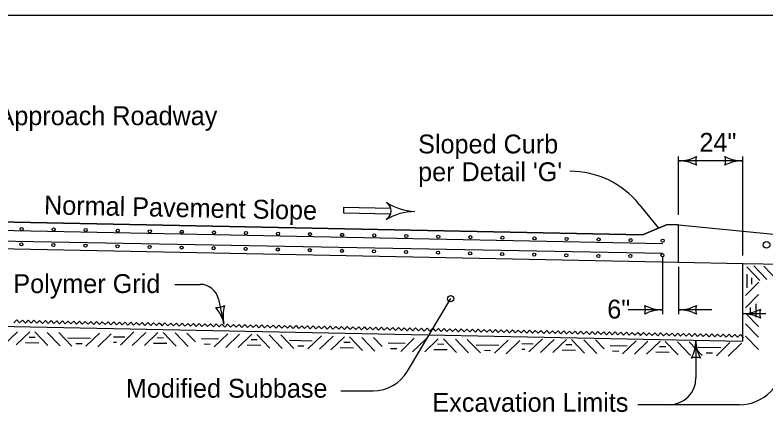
# Model space of a CAD drawing. Extents: x -2135039 to -2120895, y -2139150 to -2136566.
# Drawn here: x -2123840 to -2123042, y -2137468 to -2137036 of the extents above; entities that cross this region are included whole.
import ezdxf

# ---------------------------------------------------------------- set-up
doc = ezdxf.new("R2010")
doc.units = 0
for name, color, linetype in [('dsnCellElements', 7, 'Continuous'), ('Level 1', 7, 'Continuous'), ('Level 2', 7, 'Continuous'), ('Level 3', 7, 'Continuous')]:
    doc.layers.add(name, color=color, linetype=linetype)

msp = doc.modelspace()

# ---------------------------------------------------------------- linework, layer by layer
at = {"layer": 'dsnCellElements'}
msp.add_circle((-2123041.76, -2137279.72), 3.54, dxfattribs=at)
at = {"layer": 'Level 1'}
msp.add_lwpolyline([(-2124134.46, -2137035.95), (-2120999.47, -2137035.95), (-2120999.47, -2139045.94), (-2124134.46, -2139045.94)], close=True, dxfattribs=at)
at = {"layer": 'Level 2'}
for p, q in [((-2123135.19, -2137248.08), (-2123135.19, -2137185.93)), ((-2123067.14, -2137190.66), (-2123135.19, -2137190.66)), ((-2123067.14, -2137290.93), (-2123067.14, -2137185.93)), ((-2123176.93, -2137236.91), (-2123156.66, -2137262.08)), ((-2123440.9, -2137246.72), (-2123440.9, -2137246.72)), ((-2123440.84, -2137240.86), (-2123440.84, -2137240.86)), ((-2123173.47, -2137269.05), (-2123883.73, -2137254.79)), ((-2123883.73, -2137254.79), (-2123173.47, -2137269.05)), ((-2123883.73, -2137263.74), (-2123152.03, -2137278.43)), ((-2123147.96, -2137258.47), (-2123173.47, -2137269.05)), ((-2123173.47, -2137269.05), (-2123147.96, -2137258.47)), ((-2123135.19, -2137258.47), (-2123147.96, -2137258.47)), ((-2123135.19, -2137258.47), (-2123147.96, -2137258.47)), ((-2123135.19, -2137298.18), (-2123135.19, -2137258.47)), ((-2123135.19, -2137298.18), (-2123135.19, -2137258.47)), ((-2123135.19, -2137258.47), (-2123022.92, -2137269.7)), ((-2123884.3, -2137283.15), (-2123135.19, -2137298.18)), ((-2123883.16, -2137283.17), (-2123135.19, -2137298.18)), ((-2123152.21, -2137292.66), (-2123152.21, -2137353.4)), ((-2123135.19, -2137298.18), (-2123067.14, -2137299.55)), ((-2123135.19, -2137302.91), (-2123135.19, -2137353.4)), ((-2123067.14, -2137381.97), (-2123067.14, -2137299.55)), ((-2123067.14, -2137299.55), (-2122889.28, -2137303.12)), ((-2123062.64, -2137303.03), (-2123048.78, -2137317.45)), ((-2123055.42, -2137302.1), (-2123041.56, -2137316.52)), ((-2123044.56, -2137302.43), (-2123031.18, -2137316.36)), ((-2123064.1, -2137333.65), (-2123049.96, -2137319.51)), ((-2123670.01, -2137321.68), (-2123643.2, -2137321.68)), ((-2123064.33, -2137346.66), (-2123050.19, -2137332.52)), ((-2123623.67, -2137337.38), (-2123617.85, -2137363.75)), ((-2123622.24, -2137343.83), (-2123621.12, -2137348.94)), ((-2123423.08, -2137413.8), (-2123377.06, -2137336.83)), ((-2123152.21, -2137348.68), (-2123188.75, -2137348.68)), ((-2123099.97, -2137348.68), (-2123135.19, -2137348.68)), ((-2123064.33, -2137352.07), (-2123050.19, -2137366.21)), ((-2123042.42, -2137352.8), (-2123067.14, -2137352.8)), ((-2123883.73, -2137365.58), (-2123067.14, -2137381.97)), ((-2123064.33, -2137363.65), (-2123050.19, -2137377.79)), ((-2123837.07, -2137372), (-2123851.49, -2137385.86)), ((-2123824.06, -2137372.04), (-2123838.48, -2137385.89)), ((-2123818.65, -2137372.15), (-2123804.79, -2137386.57)), ((-2123805.64, -2137372.63), (-2123791.79, -2137387.06)), ((-2123793.19, -2137372.66), (-2123779.34, -2137387.08)), ((-2123749.98, -2137373.52), (-2123764.4, -2137387.38)), ((-2123737.53, -2137374), (-2123751.96, -2137387.85)), ((-2123713.44, -2137372.17), (-2123727.86, -2137386.02)), ((-2123701, -2137372.64), (-2123715.42, -2137386.5)), ((-2123687.99, -2137372.68), (-2123702.41, -2137386.53)), ((-2123682.58, -2137372.78), (-2123668.72, -2137387.21)), ((-2123669.57, -2137373.27), (-2123655.72, -2137387.69)), ((-2123657.12, -2137373.3), (-2123648.02, -2137382.77)), ((-2123613.91, -2137374.16), (-2123628.33, -2137388.02)), ((-2123601.46, -2137374.64), (-2123615.89, -2137388.49)), ((-2123588.45, -2137374.67), (-2123602.88, -2137388.53)), ((-2123583.04, -2137374.78), (-2123569.19, -2137389.21)), ((-2123570.04, -2137375.27), (-2123556.19, -2137389.69)), ((-2123557.59, -2137375.29), (-2123543.73, -2137389.72)), ((-2123514.38, -2137376.16), (-2123528.8, -2137390.02)), ((-2123501.93, -2137376.64), (-2123516.36, -2137390.49)), ((-2123489.88, -2137377.39), (-2123504.31, -2137391.25)), ((-2123484.47, -2137377.5), (-2123470.62, -2137391.92)), ((-2123471.47, -2137377.99), (-2123457.62, -2137392.41)), ((-2123459.02, -2137378.01), (-2123449.92, -2137387.49)), ((-2123415.8, -2137378.88), (-2123430.23, -2137392.74)), ((-2123403.36, -2137379.36), (-2123417.78, -2137393.21)), ((-2123390.35, -2137379.39), (-2123404.77, -2137393.25)), ((-2123384.94, -2137379.5), (-2123371.09, -2137393.92)), ((-2123371.94, -2137379.99), (-2123358.08, -2137394.41)), ((-2123359.49, -2137380.01), (-2123345.63, -2137394.43)), ((-2123316.27, -2137380.88), (-2123330.7, -2137394.73)), ((-2123303.83, -2137381.35), (-2123318.25, -2137395.21)), ((-2123279.74, -2137379.52), (-2123294.16, -2137393.37)), ((-2123267.29, -2137380), (-2123281.72, -2137393.85)), ((-2123254.28, -2137380.03), (-2123268.71, -2137393.89)), ((-2123248.87, -2137380.14), (-2123235.02, -2137394.56)), ((-2123235.87, -2137380.63), (-2123222.02, -2137395.05)), ((-2123223.42, -2137380.65), (-2123214.32, -2137390.12)), ((-2123180.2, -2137381.52), (-2123194.63, -2137395.37)), ((-2123167.76, -2137381.99), (-2123182.18, -2137395.85)), ((-2123154.75, -2137382.03), (-2123169.17, -2137395.88)), ((-2123149.34, -2137382.14), (-2123135.48, -2137396.56)), ((-2123136.34, -2137382.62), (-2123122.48, -2137397.05)), ((-2123123.89, -2137382.65), (-2123110.03, -2137397.07)), ((-2123116.82, -2137380.97), (-2123116.82, -2137420.98)), ((-2123080.67, -2137383.51), (-2123095.09, -2137397.37)), ((-2123068.23, -2137383.99), (-2123082.65, -2137397.85)), ((-2123064.33, -2137376.71), (-2123050.19, -2137390.85)), ((-2123493.87, -2137434.51), (-2123459.59, -2137434.51)), ((-2123070.77, -2137449.33), (-2123178.54, -2137449.33))]:
    msp.add_line(p, q, dxfattribs=at)
for points in [[(-2123440.79, -2137241.05), (-2123490.83, -2137240.04), (-2123490.95, -2137245.71), (-2123440.9, -2137246.72)], [(-2123062.52, -2137325.22), (-2123062.52, -2137311.02)], [(-2123057.43, -2137321.39), (-2123057.43, -2137314.85)], [(-2123052.97, -2137356.46), (-2123052.97, -2137342.27)], [(-2123058.83, -2137352.63), (-2123058.83, -2137346.1)], [(-2123840.85, -2137362.43), (-2123837.76, -2137359.47), (-2123834.8, -2137362.55), (-2123831.71, -2137359.58), (-2123830.23, -2137361.13)], [(-2123830.23, -2137361.13), (-2123828.75, -2137362.67), (-2123825.67, -2137359.71), (-2123822.7, -2137362.79), (-2123819.62, -2137359.83), (-2123816.65, -2137362.92), (-2123813.57, -2137359.95), (-2123810.61, -2137363.04), (-2123807.52, -2137360.07), (-2123804.56, -2137363.16), (-2123801.47, -2137360.19), (-2123798.51, -2137363.28), (-2123795.42, -2137360.32), (-2123792.46, -2137363.4), (-2123789.37, -2137360.44), (-2123786.41, -2137363.52), (-2123783.33, -2137360.56), (-2123780.36, -2137363.64), (-2123777.28, -2137360.68), (-2123774.31, -2137363.76), (-2123771.23, -2137360.8), (-2123768.26, -2137363.89), (-2123765.18, -2137360.92), (-2123762.22, -2137364.01), (-2123759.13, -2137361.04), (-2123757.65, -2137362.59)], [(-2123757.65, -2137362.59), (-2123756.17, -2137364.13), (-2123753.08, -2137361.17), (-2123750.12, -2137364.25), (-2123747.03, -2137361.29), (-2123744.07, -2137364.37), (-2123740.98, -2137361.41), (-2123738.02, -2137364.49), (-2123734.93, -2137361.53), (-2123731.97, -2137364.61), (-2123728.89, -2137361.65), (-2123725.92, -2137364.74), (-2123722.84, -2137361.77), (-2123719.87, -2137364.86), (-2123716.79, -2137361.89), (-2123713.82, -2137364.98), (-2123710.74, -2137362.01), (-2123707.78, -2137365.1), (-2123704.69, -2137362.14), (-2123701.73, -2137365.22), (-2123698.64, -2137362.26), (-2123695.68, -2137365.34), (-2123692.59, -2137362.38), (-2123689.63, -2137365.46), (-2123686.54, -2137362.5), (-2123685.06, -2137364.04)], [(-2123685.06, -2137364.04), (-2123683.58, -2137365.58), (-2123680.5, -2137362.62), (-2123677.53, -2137365.71), (-2123674.45, -2137362.74), (-2123671.48, -2137365.83), (-2123668.4, -2137362.86), (-2123665.43, -2137365.95), (-2123662.35, -2137362.98), (-2123659.39, -2137366.07), (-2123656.3, -2137363.11), (-2123653.34, -2137366.19), (-2123650.25, -2137363.23), (-2123647.29, -2137366.32), (-2123644.2, -2137363.35), (-2123641.24, -2137366.43), (-2123638.15, -2137363.47), (-2123635.19, -2137366.55), (-2123632.11, -2137363.59), (-2123629.14, -2137366.68), (-2123626.06, -2137363.72), (-2123623.09, -2137366.8), (-2123620.01, -2137363.84), (-2123617.05, -2137366.92), (-2123613.96, -2137363.96), (-2123612.48, -2137365.5)], [(-2123612.48, -2137365.5), (-2123611, -2137367.04), (-2123607.91, -2137364.08), (-2123604.95, -2137367.16), (-2123601.86, -2137364.2), (-2123598.9, -2137367.29), (-2123595.81, -2137364.32), (-2123592.85, -2137367.41), (-2123589.77, -2137364.44), (-2123586.8, -2137367.53), (-2123583.71, -2137364.56), (-2123580.75, -2137367.65), (-2123577.67, -2137364.69), (-2123574.7, -2137367.77), (-2123571.62, -2137364.81), (-2123568.66, -2137367.89), (-2123565.57, -2137364.93), (-2123562.6, -2137368.01), (-2123559.52, -2137365.05), (-2123556.56, -2137368.13), (-2123553.47, -2137365.17), (-2123550.51, -2137368.26), (-2123547.42, -2137365.29), (-2123544.46, -2137368.38), (-2123541.37, -2137365.41), (-2123539.89, -2137366.96)], [(-2123539.89, -2137366.96), (-2123538.41, -2137368.5), (-2123535.33, -2137365.53), (-2123532.36, -2137368.62), (-2123529.28, -2137365.66), (-2123526.31, -2137368.74), (-2123523.23, -2137365.78), (-2123520.26, -2137368.86), (-2123517.18, -2137365.9), (-2123514.22, -2137368.98), (-2123511.13, -2137366.02), (-2123508.17, -2137369.11), (-2123505.09, -2137366.14), (-2123502.12, -2137369.23), (-2123499.03, -2137366.26), (-2123496.07, -2137369.35), (-2123492.98, -2137366.38), (-2123490.02, -2137369.47), (-2123486.94, -2137366.51), (-2123483.98, -2137369.59), (-2123480.89, -2137366.63), (-2123477.92, -2137369.71), (-2123474.84, -2137366.75), (-2123471.87, -2137369.83), (-2123468.79, -2137366.87), (-2123467.31, -2137368.41)], [(-2123467.31, -2137368.41), (-2123465.83, -2137369.95), (-2123462.74, -2137366.99), (-2123459.78, -2137370.08), (-2123456.7, -2137367.12), (-2123453.73, -2137370.2), (-2123450.64, -2137367.23), (-2123447.68, -2137370.32), (-2123444.59, -2137367.35), (-2123441.63, -2137370.44), (-2123438.55, -2137367.48), (-2123435.59, -2137370.56), (-2123432.5, -2137367.6), (-2123429.53, -2137370.69), (-2123426.45, -2137367.72), (-2123423.48, -2137370.8), (-2123420.4, -2137367.84), (-2123417.44, -2137370.92), (-2123414.35, -2137367.96), (-2123411.39, -2137371.05), (-2123408.31, -2137368.09), (-2123405.34, -2137371.17), (-2123402.26, -2137368.21), (-2123399.29, -2137371.29), (-2123396.21, -2137368.32), (-2123394.73, -2137369.87)], [(-2123394.73, -2137369.87), (-2123393.24, -2137371.41), (-2123390.16, -2137368.45), (-2123387.19, -2137371.53), (-2123384.11, -2137368.57), (-2123381.15, -2137371.66), (-2123378.06, -2137368.69), (-2123375.1, -2137371.78), (-2123372.01, -2137368.81), (-2123369.04, -2137371.9), (-2123365.96, -2137368.93), (-2123363, -2137372.02), (-2123359.92, -2137369.06), (-2123356.95, -2137372.14), (-2123353.87, -2137369.18), (-2123350.9, -2137372.26), (-2123347.82, -2137369.3), (-2123344.85, -2137372.38), (-2123341.77, -2137369.42), (-2123338.81, -2137372.5), (-2123335.72, -2137369.54), (-2123332.76, -2137372.63), (-2123329.67, -2137369.66), (-2123326.71, -2137372.75), (-2123323.62, -2137369.78), (-2123322.14, -2137371.33)], [(-2123322.14, -2137371.33), (-2123320.66, -2137372.87), (-2123317.57, -2137369.9), (-2123314.61, -2137372.99), (-2123311.52, -2137370.03), (-2123308.56, -2137373.11), (-2123305.48, -2137370.15), (-2123302.51, -2137373.23), (-2123299.43, -2137370.27), (-2123296.46, -2137373.35), (-2123293.38, -2137370.39), (-2123290.41, -2137373.48), (-2123287.33, -2137370.51), (-2123284.37, -2137373.6), (-2123281.28, -2137370.63), (-2123278.32, -2137373.72), (-2123275.23, -2137370.75), (-2123272.27, -2137373.84), (-2123269.18, -2137370.88), (-2123266.22, -2137373.96), (-2123263.13, -2137371), (-2123260.17, -2137374.08), (-2123257.09, -2137371.12), (-2123254.12, -2137374.2), (-2123251.04, -2137371.24), (-2123249.56, -2137372.78)], [(-2123249.56, -2137372.78), (-2123248.07, -2137374.32), (-2123244.99, -2137371.36), (-2123242.02, -2137374.45), (-2123238.94, -2137371.48), (-2123235.98, -2137374.57), (-2123232.89, -2137371.6), (-2123229.93, -2137374.69), (-2123226.84, -2137371.72), (-2123223.88, -2137374.81), (-2123220.79, -2137371.85), (-2123217.83, -2137374.93), (-2123214.74, -2137371.97), (-2123211.78, -2137375.06), (-2123208.7, -2137372.09), (-2123205.73, -2137375.17), (-2123202.65, -2137372.21), (-2123199.68, -2137375.29), (-2123196.6, -2137372.33), (-2123193.63, -2137375.42), (-2123190.55, -2137372.46), (-2123187.59, -2137375.54), (-2123184.5, -2137372.58), (-2123181.54, -2137375.66), (-2123178.45, -2137372.69), (-2123176.97, -2137374.24)], [(-2123176.97, -2137374.24), (-2123175.49, -2137375.78), (-2123172.4, -2137372.82), (-2123169.44, -2137375.9), (-2123166.35, -2137372.94), (-2123163.39, -2137376.03), (-2123160.31, -2137373.06), (-2123157.34, -2137376.15), (-2123154.26, -2137373.18), (-2123151.29, -2137376.26), (-2123148.21, -2137373.3), (-2123145.24, -2137376.39), (-2123142.16, -2137373.43), (-2123139.19, -2137376.51), (-2123136.11, -2137373.55), (-2123133.15, -2137376.63), (-2123130.06, -2137373.67), (-2123127.1, -2137376.75), (-2123124.01, -2137373.79), (-2123121.05, -2137376.87), (-2123117.96, -2137373.91), (-2123115, -2137377), (-2123111.92, -2137374.03), (-2123108.95, -2137377.12), (-2123105.87, -2137374.15), (-2123104.38, -2137375.7)], [(-2123104.38, -2137375.7), (-2123102.9, -2137377.24), (-2123099.82, -2137374.27), (-2123096.85, -2137377.36), (-2123093.77, -2137374.4), (-2123090.81, -2137377.48), (-2123087.72, -2137374.52), (-2123084.76, -2137377.6), (-2123081.67, -2137374.64), (-2123078.71, -2137377.72), (-2123075.62, -2137374.76), (-2123072.66, -2137377.85), (-2123069.57, -2137374.88), (-2123066.61, -2137377.97), (-2123066.39, -2137377.78)], [(-2123828.67, -2137383.3), (-2123814.48, -2137383.59)], [(-2123824.73, -2137377.52), (-2123818.19, -2137377.65)], [(-2123783.72, -2137378.32), (-2123759.67, -2137378.81)], [(-2123735.27, -2137383), (-2123732.01, -2137383.07)], [(-2123735.16, -2137377.21), (-2123723.13, -2137377.45)], [(-2123692.6, -2137383.94), (-2123678.41, -2137384.22)], [(-2123688.66, -2137378.16), (-2123682.12, -2137378.29)], [(-2123641.66, -2137379.08), (-2123623.6, -2137379.44)], [(-2123589.12, -2137380.16), (-2123582.59, -2137380.29)], [(-2123548.12, -2137380.96), (-2123524.06, -2137381.44)], [(-2123490.55, -2137382.88), (-2123484.02, -2137383.01)], [(-2123443.56, -2137383.8), (-2123425.49, -2137384.16)], [(-2123775.08, -2137384.3), (-2123768.55, -2137384.43)], [(-2123639.01, -2137384.94), (-2123632.48, -2137385.07)], [(-2123593.07, -2137385.94), (-2123578.88, -2137386.22)], [(-2123539.47, -2137386.93), (-2123532.94, -2137387.06)], [(-2123494.5, -2137388.66), (-2123480.31, -2137388.94)], [(-2123440.9, -2137389.65), (-2123434.37, -2137389.78)], [(-2123394.97, -2137390.65), (-2123380.78, -2137390.94)], [(-2123391.02, -2137384.88), (-2123384.49, -2137385.01)], [(-2123350.02, -2137385.68), (-2123325.96, -2137386.16)], [(-2123341.37, -2137391.65), (-2123334.84, -2137391.78)], [(-2123301.57, -2137390.36), (-2123298.31, -2137390.42)], [(-2123301.45, -2137384.56), (-2123289.43, -2137384.8)], [(-2123258.9, -2137391.29), (-2123244.71, -2137391.58)], [(-2123254.95, -2137385.52), (-2123248.42, -2137385.65)], [(-2123207.96, -2137386.44), (-2123189.89, -2137386.8)], [(-2123155.42, -2137387.51), (-2123148.89, -2137387.64)], [(-2123114.42, -2137388.31), (-2123090.36, -2137388.8)], [(-2123205.3, -2137392.29), (-2123198.77, -2137392.42)], [(-2123159.37, -2137393.29), (-2123145.18, -2137393.58)], [(-2123105.77, -2137394.29), (-2123099.24, -2137394.42)]]:
    msp.add_lwpolyline(points, dxfattribs=at)
for centre, radius in [((-2123832.71, -2137262.85), 1.65), ((-2123798.68, -2137263.47), 1.65), ((-2123764.65, -2137264.1), 1.65), ((-2123730.61, -2137264.72), 1.65), ((-2123696.58, -2137265.35), 1.65), ((-2123662.55, -2137265.98), 1.65), ((-2123628.51, -2137266.6), 1.65), ((-2123594.48, -2137267.23), 1.65), ((-2123560.45, -2137267.86), 1.65), ((-2123526.41, -2137268.48), 1.65), ((-2123492.38, -2137269.11), 1.65), ((-2123458.34, -2137269.73), 1.65), ((-2123424.31, -2137270.36), 1.65), ((-2123390.28, -2137270.99), 1.65), ((-2123356.24, -2137271.61), 1.65), ((-2123322.21, -2137272.24), 1.65), ((-2123288.18, -2137272.87), 1.65), ((-2123254.14, -2137273.49), 1.65), ((-2123220.11, -2137274.12), 1.65), ((-2123832.99, -2137279.22), 1.65), ((-2123798.96, -2137279.9), 1.65), ((-2123764.92, -2137280.59), 1.65), ((-2123730.89, -2137281.27), 1.65), ((-2123696.86, -2137281.95), 1.65), ((-2123186.07, -2137274.74), 1.65), ((-2123152.04, -2137275.37), 1.65), ((-2123662.83, -2137282.64), 1.65), ((-2123628.79, -2137283.32), 1.65), ((-2123594.76, -2137284), 1.65), ((-2123560.73, -2137284.68), 1.65), ((-2123526.7, -2137285.37), 1.65), ((-2123492.66, -2137286.05), 1.65), ((-2123458.63, -2137286.73), 1.65), ((-2123424.6, -2137287.42), 1.65), ((-2123390.57, -2137288.1), 1.65), ((-2123356.53, -2137288.78), 1.65), ((-2123322.5, -2137289.47), 1.65), ((-2123288.47, -2137290.15), 1.65), ((-2123254.44, -2137290.83), 1.65), ((-2123220.4, -2137291.52), 1.65), ((-2123186.38, -2137291.52), 1.65), ((-2123152.35, -2137290.83), 1.65), ((-2123377.06, -2137336.83), 3.31)]:
    msp.add_circle(centre, radius, dxfattribs=at)
for centre, radius, start, end in [((-2123135.19, -2137150.48), 40.18, 270, 298.07249), ((-2123135.19, -2137150.48), 40.18, 270, 298.07249), ((-2123135.19, -2137230.83), 40.18, 61.92751, 90), ((-2123135.19, -2137230.83), 40.18, 61.92751, 90), ((-2123101.51, -2137190.65), 15.52, 162.26665, 197.73335), ((-2123101.51, -2137190.65), 15.52, 162.26665, 197.73335), ((-2123100.82, -2137190.65), 15.52, 342.26665, 17.73335), ((-2123067.13, -2137150.48), 40.18, 241.92751, 270), ((-2123100.82, -2137190.65), 15.52, 342.26665, 17.73335), ((-2123067.13, -2137150.48), 40.18, 241.92751, 270), ((-2123067.13, -2137230.83), 40.18, 90, 118.07249), ((-2123067.13, -2137230.83), 40.18, 90, 118.07249), ((-2123250.56, -2137296.19), 94.53, 38.83776, 90), ((-2123451.13, -2137243.67), 10.67, 300.56474, 57.13538), ((-2123412.26, -2137183.52), 60.95, 237.1358, 267.16583), ((-2123412.26, -2137183.52), 60.95, 237.13627, 267.16583), ((-2123451.13, -2137243.67), 10.67, 14.25957, 57.13267), ((-2123414.71, -2137305.34), 60.95, 90.53429, 120.56432), ((-2123414.71, -2137305.34), 60.95, 90.53429, 120.56385), ((-2123451.13, -2137243.67), 10.67, 300.56746, 343.42998), ((-2123643.2, -2137341.68), 20, 12.43142, 90), ((-2123625.1, -2137330.85), 15.52, 264.68499, 300.15169), ((-2123578.62, -2137355.11), 40.18, 164.34585, 192.41834), ((-2123185.89, -2137348.68), 15.52, 342.26665, 17.73335), ((-2123152.21, -2137308.5), 40.18, 241.92751, 270), ((-2123135.19, -2137308.5), 40.18, 270, 298.07249), ((-2123101.51, -2137348.68), 15.52, 162.26665, 197.73335), ((-2123657.09, -2137372.39), 40.18, 12.41834, 40.49083), ((-2123152.21, -2137388.85), 40.18, 90, 118.07249), ((-2123135.19, -2137388.85), 40.18, 61.92751, 90), ((-2123067.13, -2137312.63), 40.18, 270, 298.07249), ((-2123033.45, -2137352.8), 15.52, 162.26665, 197.73335), ((-2123067.13, -2137392.98), 40.18, 61.92751, 90), ((-2123156.99, -2137380.97), 40.18, 331.92751, 360), ((-2123076.64, -2137380.97), 40.18, 180, 208.07249), ((-2123116.82, -2137414.66), 15.52, 72.26665, 107.73335), ((-2123070.77, -2137402.07), 47.27, 270, 360), ((-2123459.59, -2137391.97), 42.54, 270, 329.12488), ((-2123145.18, -2137420.98), 28.36, 270, 360)]:
    msp.add_arc(centre, radius, start, end, dxfattribs=at)
at = {"layer": 'Level 3'}
msp.add_line((-2123152.22, -2137288.89), (-2123883.77, -2137275.34), dxfattribs=at)

# ---------------------------------------------------------------- texts
for s, p in [('Approach Roadway', (-2123858.32, -2137152.8)), ('24"', (-2123113.07, -2137181.01)), ('Sloped Curb', (-2123411.71, -2137182.76)), ("per Detail 'G'", (-2123411.71, -2137212.21)), ('Polymer Grid', (-2123841.5, -2137330.88)), ('6"', (-2123210.93, -2137357.93)), ('Modified Subbase', (-2123722.06, -2137441.91)), ('Excavation Limits', (-2123396.57, -2137456.85))]:
    msp.add_text(s, height=20, dxfattribs=at).set_placement(p)
msp.add_text('Normal Pavement Slope', height=20, rotation=358.85018, dxfattribs=at).set_placement((-2123809.03, -2137247.37))

doc.saveas('drawing.dxf')
